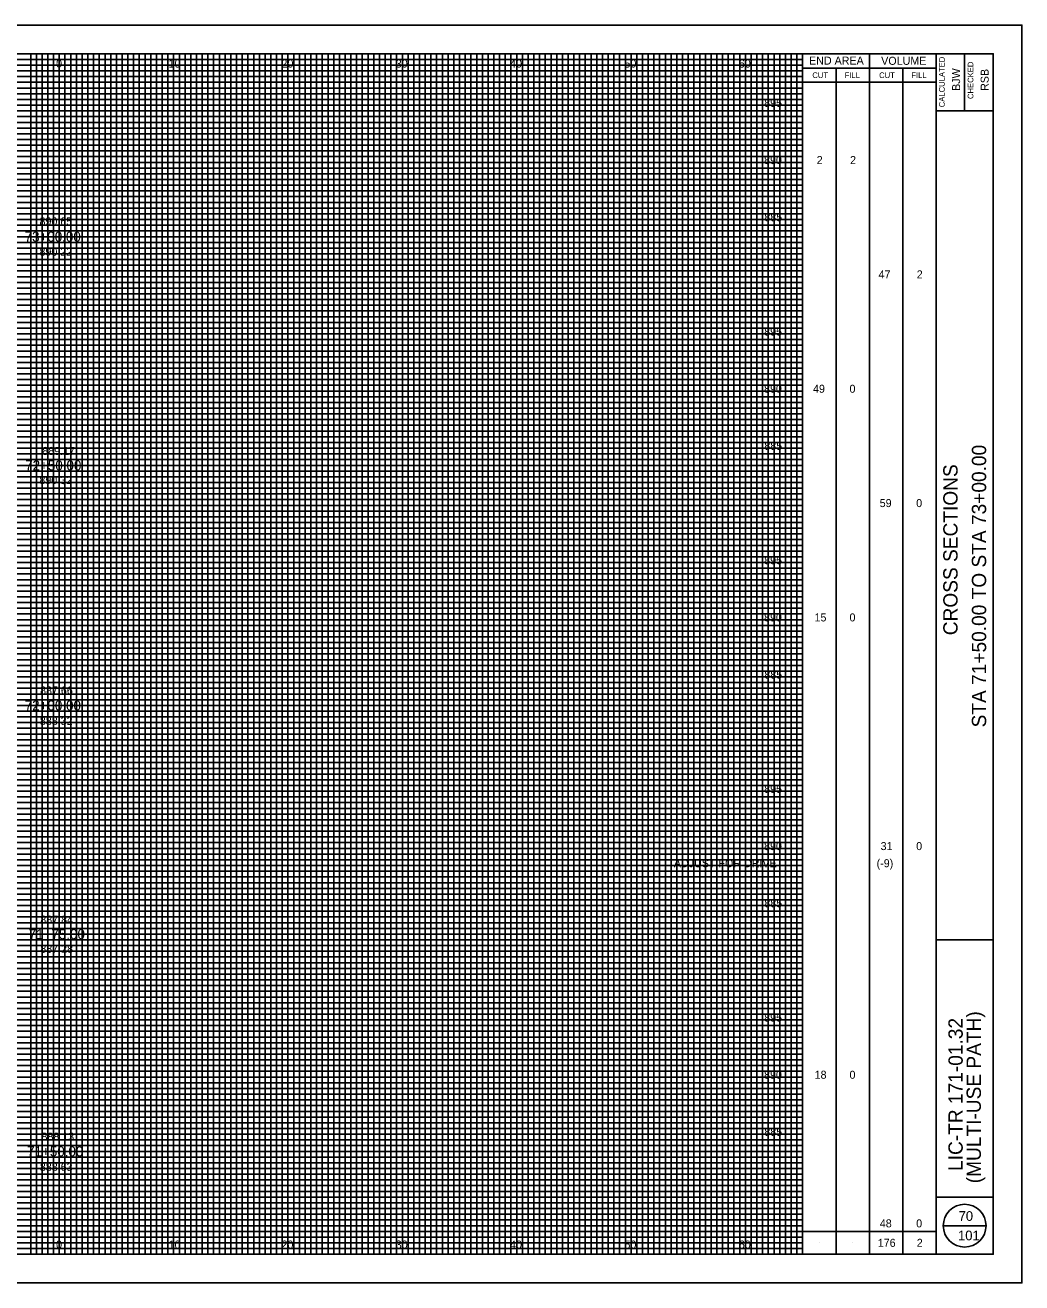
# Model space of a CAD drawing. Extents: x -10 to 160, y -2 to 3672.
# Drawn here: x 72.8 to 160, y 112.5 to 222.5 of the extents above; entities that cross this region are included whole.
import ezdxf

# ---------------------------------------------------------------- set-up
doc = ezdxf.new("R2010")
doc.units = 0
for name, color, linetype in [('SH_Border', 7, 'Continuous'), ('SH_Cut_Line', 7, 'Continuous'), ('SH_Data', 7, 'Continuous'), ('SH_Major_Grid_Line', 7, 'Continuous'), ('SH_Minor_Grid_Line', 7, 'Continuous'), ('SH_Text', 7, 'Continuous'), ('TX_P_10', 7, 'Continuous'), ('TX_X_10', 7, 'Continuous')]:
    doc.layers.add(name, color=color, linetype=linetype)

msp = doc.modelspace()

# ---------------------------------------------------------------- linework, layer by layer
at = {"layer": 'SH_Border'}
for p, q in [((152.5, 115), (152.5, 220)), ((155, 220), (155, 215)), ((152.5, 215), (157.5, 215)), ((152.5, 142.5), (157.5, 142.5)), ((152.5, 120), (157.5, 120))]:
    msp.add_line(p, q, dxfattribs=at)
msp.add_lwpolyline([(0, 220), (157.5, 220), (157.5, 115), (0, 115)], close=True, dxfattribs=at)
at = {"layer": 'SH_Cut_Line'}
msp.add_lwpolyline([(-10, 112.5), (160, 112.5), (160, 222.5), (-10, 222.5)], close=True, dxfattribs=at)
at = {"layer": 'SH_Data'}
for p, q in [((140.83, 115), (140.83, 220)), ((146.67, 115), (146.67, 220)), ((140.83, 218.75), (152.5, 218.75)), ((143.75, 115), (143.75, 218.75)), ((149.58, 115), (149.58, 218.75)), ((140.83, 217.5), (152.5, 217.5)), ((140.83, 117), (152.5, 117)), ((153.12, 117.5), (156.88, 117.5)), ((142.29, 116), (142.29, 116)), ((145.21, 116), (145.21, 116)), ((148.12, 116), (148.12, 116)), ((151.04, 116), (151.04, 116))]:
    msp.add_line(p, q, dxfattribs=at)
msp.add_circle((155, 117.5), 1.87, dxfattribs=at)
at = {"layer": 'SH_Major_Grid_Line'}
for p, q in [((75.83, 115), (75.83, 220)), ((80.83, 115), (80.83, 220)), ((85.83, 115), (85.83, 220)), ((90.83, 115), (90.83, 220)), ((95.83, 115), (95.83, 220)), ((100.83, 115), (100.83, 220)), ((105.83, 115), (105.83, 220)), ((110.83, 115), (110.83, 220)), ((115.83, 115), (115.83, 220)), ((120.83, 115), (120.83, 220)), ((125.83, 115), (125.83, 220)), ((130.83, 115), (130.83, 220)), ((135.83, 115), (135.83, 220)), ((5.83, 215), (140.83, 215)), ((5.83, 210), (140.83, 210)), ((5.83, 205), (140.83, 205)), ((5.83, 200), (140.83, 200)), ((5.83, 195), (140.83, 195)), ((5.83, 190), (140.83, 190)), ((5.83, 185), (140.83, 185)), ((5.83, 180), (140.83, 180)), ((5.83, 175), (140.83, 175)), ((5.83, 170), (140.83, 170)), ((5.83, 165), (140.83, 165)), ((5.83, 160), (140.83, 160)), ((5.83, 155), (140.83, 155)), ((5.83, 150), (140.83, 150)), ((5.83, 145), (140.83, 145)), ((5.83, 140), (140.83, 140)), ((5.83, 135), (140.83, 135)), ((5.83, 130), (140.83, 130)), ((5.83, 125), (140.83, 125)), ((5.83, 120), (140.83, 120))]:
    msp.add_line(p, q, dxfattribs=at)
at = {"layer": 'SH_Minor_Grid_Line'}
for p, q in [((5.83, 219.5), (140.83, 219.5)), ((5.83, 219), (140.83, 219)), ((73.33, 115), (73.33, 220)), ((73.83, 115), (73.83, 220)), ((74.33, 115), (74.33, 220)), ((74.83, 115), (74.83, 220)), ((75.33, 115), (75.33, 220)), ((76.33, 115), (76.33, 220)), ((76.83, 115), (76.83, 220)), ((77.33, 115), (77.33, 220)), ((77.83, 115), (77.83, 220)), ((78.33, 115), (78.33, 220)), ((78.83, 115), (78.83, 220)), ((79.33, 115), (79.33, 220)), ((79.83, 115), (79.83, 220)), ((80.33, 115), (80.33, 220)), ((81.33, 115), (81.33, 220)), ((81.83, 115), (81.83, 220)), ((82.33, 115), (82.33, 220)), ((82.83, 115), (82.83, 220)), ((83.33, 115), (83.33, 220)), ((83.83, 115), (83.83, 220)), ((84.33, 115), (84.33, 220)), ((84.83, 115), (84.83, 220)), ((85.33, 115), (85.33, 220)), ((86.33, 115), (86.33, 220)), ((86.83, 115), (86.83, 220)), ((87.33, 115), (87.33, 220)), ((87.83, 115), (87.83, 220)), ((88.33, 115), (88.33, 220)), ((88.83, 115), (88.83, 220)), ((89.33, 115), (89.33, 220)), ((89.83, 115), (89.83, 220)), ((90.33, 115), (90.33, 220)), ((91.33, 115), (91.33, 220)), ((91.83, 115), (91.83, 220)), ((92.33, 115), (92.33, 220)), ((92.83, 115), (92.83, 220)), ((93.33, 115), (93.33, 220)), ((93.83, 115), (93.83, 220)), ((94.33, 115), (94.33, 220)), ((94.83, 115), (94.83, 220)), ((95.33, 115), (95.33, 220)), ((96.33, 115), (96.33, 220)), ((96.83, 115), (96.83, 220)), ((97.33, 115), (97.33, 220)), ((97.83, 115), (97.83, 220)), ((98.33, 115), (98.33, 220)), ((98.83, 115), (98.83, 220)), ((99.33, 115), (99.33, 220)), ((99.83, 115), (99.83, 220)), ((100.33, 115), (100.33, 220)), ((101.33, 115), (101.33, 220)), ((101.83, 115), (101.83, 220)), ((102.33, 115), (102.33, 220)), ((102.83, 115), (102.83, 220)), ((103.33, 115), (103.33, 220)), ((103.83, 115), (103.83, 220)), ((104.33, 115), (104.33, 220)), ((104.83, 115), (104.83, 220)), ((105.33, 115), (105.33, 220)), ((106.33, 115), (106.33, 220)), ((106.83, 115), (106.83, 220)), ((107.33, 115), (107.33, 220)), ((107.83, 115), (107.83, 220)), ((108.33, 115), (108.33, 220)), ((108.83, 115), (108.83, 220)), ((109.33, 115), (109.33, 220)), ((109.83, 115), (109.83, 220)), ((110.33, 115), (110.33, 220)), ((111.33, 115), (111.33, 220)), ((111.83, 115), (111.83, 220)), ((112.33, 115), (112.33, 220)), ((112.83, 115), (112.83, 220)), ((113.33, 115), (113.33, 220)), ((113.83, 115), (113.83, 220)), ((114.33, 115), (114.33, 220)), ((114.83, 115), (114.83, 220)), ((115.33, 115), (115.33, 220)), ((116.33, 115), (116.33, 220)), ((116.83, 115), (116.83, 220)), ((117.33, 115), (117.33, 220)), ((117.83, 115), (117.83, 220)), ((118.33, 115), (118.33, 220)), ((118.83, 115), (118.83, 220)), ((119.33, 115), (119.33, 220)), ((119.83, 115), (119.83, 220)), ((120.33, 115), (120.33, 220)), ((121.33, 115), (121.33, 220)), ((121.83, 115), (121.83, 220)), ((122.33, 115), (122.33, 220)), ((122.83, 115), (122.83, 220)), ((123.33, 115), (123.33, 220)), ((123.83, 115), (123.83, 220)), ((124.33, 115), (124.33, 220)), ((124.83, 115), (124.83, 220)), ((125.33, 115), (125.33, 220)), ((126.33, 115), (126.33, 220)), ((126.83, 115), (126.83, 220)), ((127.33, 115), (127.33, 220)), ((127.83, 115), (127.83, 220)), ((128.33, 115), (128.33, 220)), ((128.83, 115), (128.83, 220)), ((129.33, 115), (129.33, 220)), ((129.83, 115), (129.83, 220)), ((130.33, 115), (130.33, 220)), ((131.33, 115), (131.33, 220)), ((131.83, 115), (131.83, 220)), ((132.33, 115), (132.33, 220)), ((132.83, 115), (132.83, 220)), ((133.33, 115), (133.33, 220)), ((133.83, 115), (133.83, 220)), ((134.33, 115), (134.33, 220)), ((134.83, 115), (134.83, 220)), ((135.33, 115), (135.33, 220)), ((136.33, 115), (136.33, 220)), ((136.83, 115), (136.83, 220)), ((137.33, 115), (137.33, 220)), ((137.83, 115), (137.83, 220)), ((138.33, 115), (138.33, 220)), ((138.83, 115), (138.83, 220)), ((139.33, 115), (139.33, 220)), ((139.83, 115), (139.83, 220)), ((140.33, 115), (140.33, 220)), ((5.83, 218.5), (140.83, 218.5)), ((5.83, 218), (140.83, 218)), ((5.83, 217.5), (140.83, 217.5)), ((5.83, 217), (140.83, 217)), ((5.83, 216.5), (140.83, 216.5)), ((5.83, 216), (140.83, 216)), ((5.83, 215.5), (140.83, 215.5)), ((5.83, 214.5), (140.83, 214.5)), ((5.83, 214), (140.83, 214)), ((5.83, 213.5), (140.83, 213.5)), ((5.83, 213), (140.83, 213)), ((5.83, 212.5), (140.83, 212.5)), ((5.83, 212), (140.83, 212)), ((5.83, 211.5), (140.83, 211.5)), ((5.83, 211), (140.83, 211)), ((5.83, 210.5), (140.83, 210.5)), ((5.83, 209.5), (140.83, 209.5)), ((5.83, 209), (140.83, 209)), ((5.83, 208.5), (140.83, 208.5)), ((5.83, 208), (140.83, 208)), ((5.83, 207.5), (140.83, 207.5)), ((5.83, 207), (140.83, 207)), ((5.83, 206.5), (140.83, 206.5)), ((5.83, 206), (140.83, 206)), ((5.83, 205.5), (140.83, 205.5)), ((5.83, 204.5), (140.83, 204.5)), ((5.83, 204), (140.83, 204)), ((5.83, 203.5), (140.83, 203.5)), ((5.83, 203), (140.83, 203)), ((5.83, 202.5), (140.83, 202.5)), ((5.83, 202), (140.83, 202)), ((5.83, 201.5), (140.83, 201.5)), ((5.83, 201), (140.83, 201)), ((5.83, 200.5), (140.83, 200.5)), ((5.83, 199.5), (140.83, 199.5)), ((5.83, 199), (140.83, 199)), ((5.83, 198.5), (140.83, 198.5)), ((5.83, 198), (140.83, 198)), ((5.83, 197.5), (140.83, 197.5)), ((5.83, 197), (140.83, 197)), ((5.83, 196.5), (140.83, 196.5)), ((5.83, 196), (140.83, 196)), ((5.83, 195.5), (140.83, 195.5)), ((5.83, 194.5), (140.83, 194.5)), ((5.83, 194), (140.83, 194)), ((5.83, 193.5), (140.83, 193.5)), ((5.83, 193), (140.83, 193)), ((5.83, 192.5), (140.83, 192.5)), ((5.83, 192), (140.83, 192)), ((5.83, 191.5), (140.83, 191.5)), ((5.83, 191), (140.83, 191)), ((5.83, 190.5), (140.83, 190.5)), ((5.83, 189.5), (140.83, 189.5)), ((5.83, 189), (140.83, 189)), ((5.83, 188.5), (140.83, 188.5)), ((5.83, 188), (140.83, 188)), ((5.83, 187.5), (140.83, 187.5)), ((5.83, 187), (140.83, 187)), ((5.83, 186.5), (140.83, 186.5)), ((5.83, 186), (140.83, 186)), ((5.83, 185.5), (140.83, 185.5)), ((5.83, 184.5), (140.83, 184.5)), ((5.83, 184), (140.83, 184)), ((5.83, 183.5), (140.83, 183.5)), ((5.83, 183), (140.83, 183)), ((5.83, 182.5), (140.83, 182.5)), ((5.83, 182), (140.83, 182)), ((5.83, 181.5), (140.83, 181.5)), ((5.83, 181), (140.83, 181)), ((5.83, 180.5), (140.83, 180.5)), ((5.83, 179.5), (140.83, 179.5)), ((5.83, 179), (140.83, 179)), ((5.83, 178.5), (140.83, 178.5)), ((5.83, 178), (140.83, 178)), ((5.83, 177.5), (140.83, 177.5)), ((5.83, 177), (140.83, 177)), ((5.83, 176.5), (140.83, 176.5)), ((5.83, 176), (140.83, 176)), ((5.83, 175.5), (140.83, 175.5)), ((5.83, 174.5), (140.83, 174.5)), ((5.83, 174), (140.83, 174)), ((5.83, 173.5), (140.83, 173.5)), ((5.83, 173), (140.83, 173)), ((5.83, 172.5), (140.83, 172.5)), ((5.83, 172), (140.83, 172)), ((5.83, 171.5), (140.83, 171.5)), ((5.83, 171), (140.83, 171)), ((5.83, 170.5), (140.83, 170.5)), ((5.83, 169.5), (140.83, 169.5)), ((5.83, 169), (140.83, 169)), ((5.83, 168.5), (140.83, 168.5)), ((5.83, 168), (140.83, 168)), ((5.83, 167.5), (140.83, 167.5)), ((5.83, 167), (140.83, 167)), ((5.83, 166.5), (140.83, 166.5)), ((5.83, 166), (140.83, 166)), ((5.83, 165.5), (140.83, 165.5)), ((5.83, 164.5), (140.83, 164.5)), ((5.83, 164), (140.83, 164)), ((5.83, 163.5), (140.83, 163.5)), ((5.83, 163), (140.83, 163)), ((5.83, 162.5), (140.83, 162.5)), ((5.83, 162), (140.83, 162)), ((5.83, 161.5), (140.83, 161.5)), ((5.83, 161), (140.83, 161)), ((5.83, 160.5), (140.83, 160.5)), ((5.83, 159.5), (140.83, 159.5)), ((5.83, 159), (140.83, 159)), ((5.83, 158.5), (140.83, 158.5)), ((5.83, 158), (140.83, 158)), ((5.83, 157.5), (140.83, 157.5)), ((5.83, 157), (140.83, 157)), ((5.83, 156.5), (140.83, 156.5)), ((5.83, 156), (140.83, 156)), ((5.83, 155.5), (140.83, 155.5)), ((5.83, 154.5), (140.83, 154.5)), ((5.83, 154), (140.83, 154)), ((5.83, 153.5), (140.83, 153.5)), ((5.83, 153), (140.83, 153)), ((5.83, 152.5), (140.83, 152.5)), ((5.83, 152), (140.83, 152)), ((5.83, 151.5), (140.83, 151.5)), ((5.83, 151), (140.83, 151)), ((5.83, 150.5), (140.83, 150.5)), ((5.83, 149.5), (140.83, 149.5)), ((5.83, 149), (140.83, 149)), ((5.83, 148.5), (140.83, 148.5)), ((5.83, 148), (140.83, 148)), ((5.83, 147.5), (140.83, 147.5)), ((5.83, 147), (140.83, 147)), ((5.83, 146.5), (140.83, 146.5)), ((5.83, 146), (140.83, 146)), ((5.83, 145.5), (140.83, 145.5)), ((5.83, 144.5), (140.83, 144.5)), ((5.83, 144), (140.83, 144)), ((5.83, 143.5), (140.83, 143.5)), ((5.83, 143), (140.83, 143)), ((5.83, 142.5), (140.83, 142.5)), ((5.83, 142), (140.83, 142)), ((5.83, 141.5), (140.83, 141.5)), ((5.83, 141), (140.83, 141)), ((5.83, 140.5), (140.83, 140.5)), ((5.83, 139.5), (140.83, 139.5)), ((5.83, 139), (140.83, 139)), ((5.83, 138.5), (140.83, 138.5)), ((5.83, 138), (140.83, 138)), ((5.83, 137.5), (140.83, 137.5)), ((5.83, 137), (140.83, 137)), ((5.83, 136.5), (140.83, 136.5)), ((5.83, 136), (140.83, 136)), ((5.83, 135.5), (140.83, 135.5)), ((5.83, 134.5), (140.83, 134.5)), ((5.83, 134), (140.83, 134)), ((5.83, 133.5), (140.83, 133.5)), ((5.83, 133), (140.83, 133)), ((5.83, 132.5), (140.83, 132.5)), ((5.83, 132), (140.83, 132)), ((5.83, 131.5), (140.83, 131.5)), ((5.83, 131), (140.83, 131)), ((5.83, 130.5), (140.83, 130.5)), ((5.83, 129.5), (140.83, 129.5)), ((5.83, 129), (140.83, 129)), ((5.83, 128.5), (140.83, 128.5)), ((5.83, 128), (140.83, 128)), ((5.83, 127.5), (140.83, 127.5)), ((5.83, 127), (140.83, 127)), ((5.83, 126.5), (140.83, 126.5)), ((5.83, 126), (140.83, 126)), ((5.83, 125.5), (140.83, 125.5)), ((5.83, 124.5), (140.83, 124.5)), ((5.83, 124), (140.83, 124)), ((5.83, 123.5), (140.83, 123.5)), ((5.83, 123), (140.83, 123)), ((5.83, 122.5), (140.83, 122.5)), ((5.83, 122), (140.83, 122)), ((5.83, 121.5), (140.83, 121.5)), ((5.83, 121), (140.83, 121)), ((5.83, 120.5), (140.83, 120.5)), ((5.83, 119.5), (140.83, 119.5)), ((5.83, 119), (140.83, 119)), ((5.83, 118.5), (140.83, 118.5)), ((5.83, 118), (140.83, 118)), ((5.83, 117.5), (140.83, 117.5)), ((5.83, 117), (140.83, 117)), ((5.83, 116.5), (140.83, 116.5)), ((5.83, 116), (140.83, 116)), ((5.83, 115.5), (140.83, 115.5))]:
    msp.add_line(p, q, dxfattribs=at)

# ---------------------------------------------------------------- texts
at = {"layer": 'SH_Data'}
for s, height, p in [('END AREA', 0.7, (141.39, 219.05)), ('VOLUME', 0.7, (147.7, 219.03)), ('CUT', 0.5, (141.68, 217.87)), ('FILL', 0.5, (144.5, 217.87)), ('CUT', 0.5, (147.52, 217.87)), ('FILL', 0.5, (150.34, 217.87)), ('70', 0.85, (154.47, 117.92)), ('101', 0.85, (154.42, 116.22))]:
    msp.add_text(s, height=height, dxfattribs=at).set_placement(p)
for s, height, p in [('CALCULATED', 0.5, (153.26, 215.32)), ('CHECKED', 0.5, (155.76, 216.04)), ('BJW', 0.7, (154.6, 216.75)), ('RSB', 0.7, (157.1, 216.75)), ('STA 71+50.00 TO STA 73+00.00', 1.25, (156.88, 161.08)), ('CROSS SECTIONS', 1.25, (154.38, 169.14)), ('LIC-TR 171-01.32', 1.25, (154.83, 122.29)), ('(MULTI-USE PATH)', 1.25, (156.42, 121.21))]:
    msp.add_text(s, height=height, rotation=90, dxfattribs=at).set_placement(p)
at = {"layer": 'SH_Text'}
for s, height, p in [('0', 0.7, (75.55, 218.79)), ('10', 0.7, (85.39, 218.79)), ('20', 0.7, (95.26, 218.79)), ('30', 0.7, (105.25, 218.79)), ('40', 0.7, (115.25, 218.79)), ('50', 0.7, (125.25, 218.79)), ('60', 0.7, (135.25, 218.79)), ('895', 0.7, (137.47, 215.35)), ('890', 0.7, (137.46, 210.35)), ('2', 0.7, (142.06, 210.35)), ('2', 0.7, (144.98, 210.35)), ('885', 0.7, (137.48, 205.35)), ('73+00.00', 0.875, (72.8, 203.56)), ('47', 0.7, (147.47, 200.35)), ('2', 0.7, (150.81, 200.35)), ('895', 0.7, (137.47, 195.35)), ('890', 0.7, (137.46, 190.35)), ('49', 0.7, (141.74, 190.35)), ('0', 0.7, (144.93, 190.35)), ('885', 0.7, (137.48, 185.35)), ('72+50.00', 0.875, (72.85, 183.56)), ('59', 0.7, (147.57, 180.35)), ('0', 0.7, (150.76, 180.35)), ('895', 0.7, (137.47, 175.35)), ('890', 0.7, (137.46, 170.35)), ('15', 0.7, (141.87, 170.35)), ('0', 0.7, (144.93, 170.35)), ('885', 0.7, (137.48, 165.35)), ('72+00.00', 0.875, (72.81, 162.56)), ('895', 0.7, (137.47, 155.35)), ('890', 0.7, (137.46, 150.35)), ('31', 0.7, (147.65, 150.35)), ('0', 0.7, (150.76, 150.35)), ('ADJUST FOR DRIVE', 0.7, (129.57, 148.85)), ('(-9)', 0.7, (147.3, 148.85)), ('885', 0.7, (137.48, 145.35)), ('71+75.00', 0.875, (73.16, 142.56)), ('895', 0.7, (137.47, 135.35)), ('890', 0.7, (137.46, 130.35)), ('18', 0.7, (141.88, 130.35)), ('0', 0.7, (144.93, 130.35)), ('885', 0.7, (137.48, 125.35)), ('71+50.00', 0.875, (73.02, 123.56)), ('48', 0.7, (147.58, 117.35)), ('0', 0.7, (150.76, 117.35)), ('0', 0.7, (75.55, 115.5)), ('10', 0.7, (85.39, 115.5)), ('20', 0.7, (95.26, 115.5)), ('30', 0.7, (105.25, 115.5)), ('40', 0.7, (115.25, 115.5)), ('50', 0.7, (125.25, 115.5)), ('60', 0.7, (135.25, 115.5)), ('176', 0.7, (147.4, 115.65)), ('2', 0.7, (150.81, 115.65))]:
    msp.add_text(s, height=height, dxfattribs=at).set_placement(p)
at = {"layer": 'TX_P_10'}
for s, p in [('890.65', (74.1, 204.99)), ('889.17', (74.34, 184.91)), ('887.66', (74.15, 163.96)), ('887.84', (74.17, 143.92)), ('888.13', (74.27, 124.94))]:
    msp.add_text(s, height=0.7, dxfattribs=at).set_placement(p)
at = {"layer": 'TX_X_10'}
for s, p in [('890.22', (74.1, 202.33)), ('890.32', (74.09, 182.36)), ('888.32', (74.13, 161.29)), ('887.28', (74.17, 141.37)), ('888.63', (74.13, 122.28))]:
    msp.add_text(s, height=0.7, dxfattribs=at).set_placement(p)

doc.saveas('drawing.dxf')
